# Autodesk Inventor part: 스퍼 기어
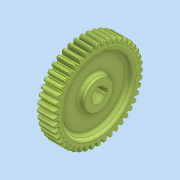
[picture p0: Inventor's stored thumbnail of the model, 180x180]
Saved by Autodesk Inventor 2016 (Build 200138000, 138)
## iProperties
Created: 2024-08
Part Number: 스퍼 기어
Material: 일반
Document SubType Name: Modeling
Designer: pc-7
Density: 1 g/cm^3
Appearance: 기본값
Author: jhkim
Sending System: Autodesk Inventor 2025
Preprocessor: ST-DEVELOPER v20
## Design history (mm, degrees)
node "스퍼 기어1"
node "솔리드2"
node "솔리드1"
